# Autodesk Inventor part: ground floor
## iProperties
Created: 2018-12
Part Number: ground floor
Document SubType Name: Modeling
Designer: Harindersingh
Density: 1 g/cm^3
Author: Harindersingh
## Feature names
1. Extrusion1
2. Extrusion2
3. Extrusion3
4. Extrusion4
5. Extrusion5
6. Extrusion6
7. Extrusion7
8. Extrusion8
9. Extrusion14
10. Extrusion15
11. Extrusion16
12. Extrusion19
13. Extrusion20
14. Extrusion21
15. Extrusion22
16. Extrusion23
